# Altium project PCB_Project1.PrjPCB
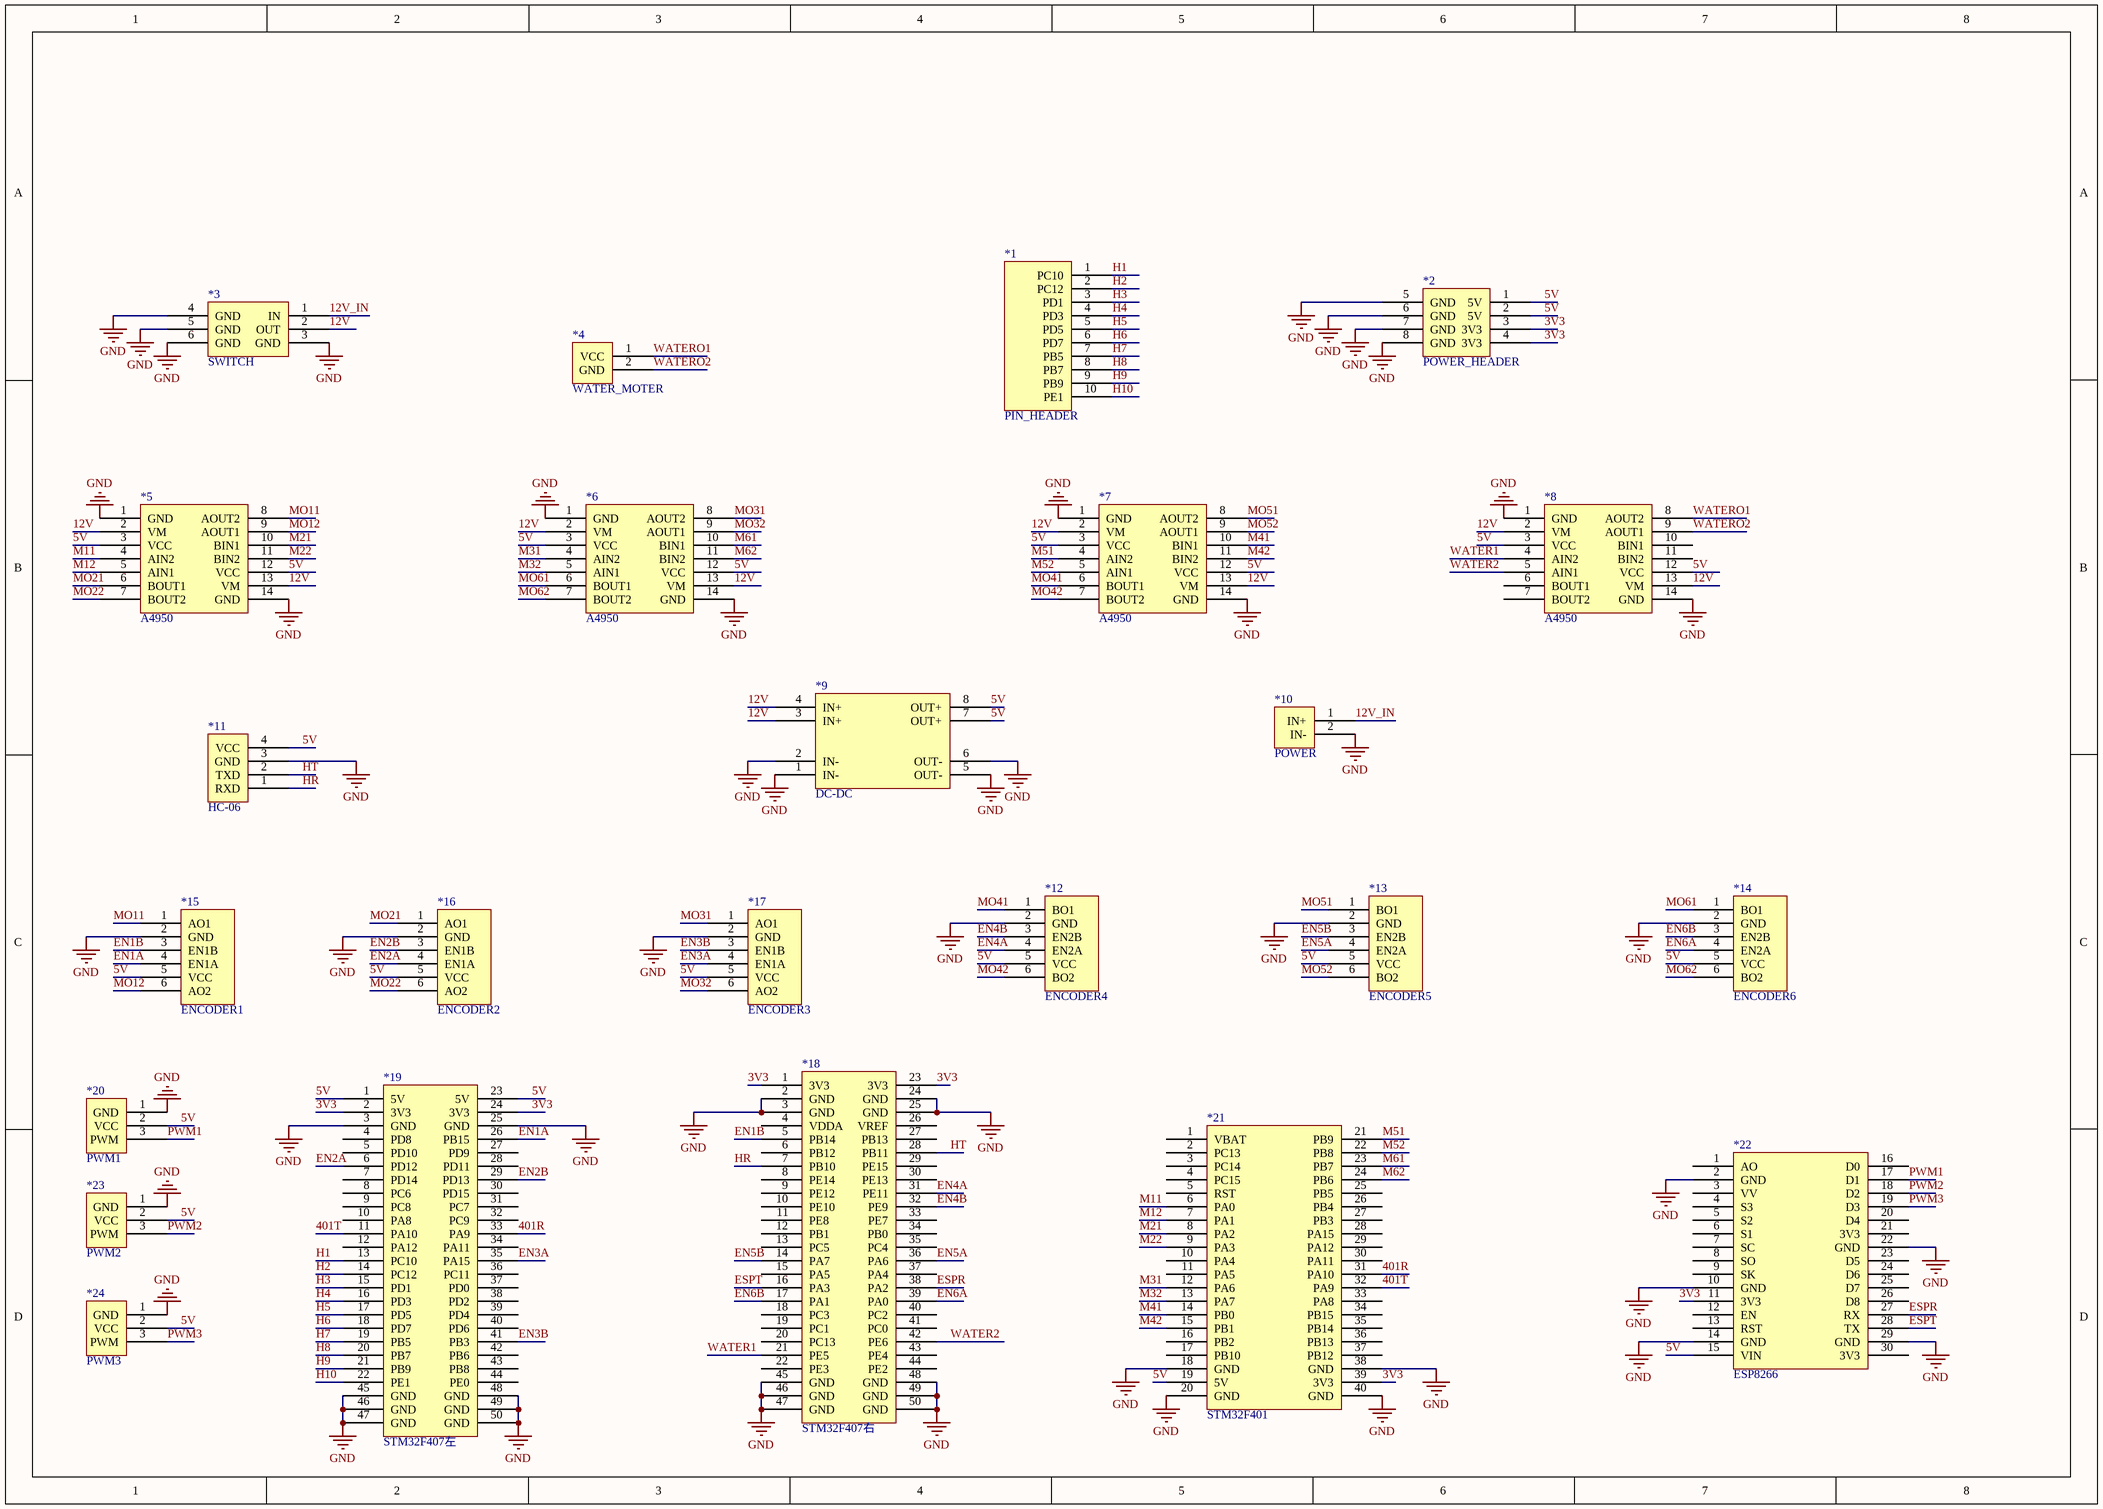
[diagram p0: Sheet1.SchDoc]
1 sheet, 24 parts. Net scope: global (net labels, ports and power ports of the same name join across sheets).
Board file: PCB1.PcbDoc

## Sheet Sheet1.SchDoc
size A3

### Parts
*1  PIN_HEADER  [PIN_HEADER]
*2  POWER_HEADER  [POWER_HEADER]
*3  SWITCH  [SIWITCH]
*4  WATER_MOTER  [WATER_HEADER]
*5  A4950  [A4950]
*6  A4950  [A4950]
*7  A4950  [A4950]
*8  A4950  [A4950]
*9  DC-DC  [DC-DC]
*10  POWER  [POWER]
*11  HC-06  [HC-06]
*12  ENCODER4  [ENCODER2]
*13  ENCODER5  [ENCODER2]
*14  ENCODER6  [ENCODER2]
*15  ENCODER1  [ENCODER1]
*16  ENCODER2  [ENCODER1]
*17  ENCODER3  [ENCODER1]
*18  STM32F407右  [STM32F407左]
*19  STM32F407左  [STM32F407左]
*20  PWM1  [PWM]
*21  STM32F401  [STM32F401CCU6]
*22  ESP8266  [ESP]
*23  PWM2  [PWM]
*24  PWM3  [PWM]

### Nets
GND: *2.5(GND) *2.6(GND) *2.7(GND) *2.8(GND) *3.3(GND) *3.4(GND) *3.5(GND) *3.6(GND) *5.1(GND) *5.14(GND) *6.1(GND) *6.14(GND) *7.1(GND) *7.14(GND) *8.1(GND) *8.14(GND) *9.1(IN-) *9.2(IN-) *9.5(OUT-) *9.6(OUT-) *10.2(IN-) *11.3(GND) *12.2(GND) *13.2(GND) *14.2(GND) *15.2(GND) *16.2(GND) *17.2(GND) *18.2(GND) *18.3(GND) *18.24(GND) *18.25(GND) *18.45(GND) *18.46(GND) *18.47(GND) *18.48(GND) *18.49(GND) *18.50(GND) *19.3(GND) *19.25(GND) *19.45(GND) *19.46(GND) *19.47(GND) *19.48(GND) *19.49(GND) *19.50(GND) *20.1(GND) *21.18(GND) *21.20(GND) *21.38(GND) *21.40(GND) *22.2(GND) *22.10(GND) *22.14(GND) *22.22(GND) *22.29(GND) *23.1(GND) *24.1(GND)
3V3: *2.3(3V3) *2.4(3V3) *18.1(3V3) *18.23(3V3) *19.2(3V3) *19.24(3V3) *21.39(3V3) *22.11(3V3)
5V: *2.1(5V) *2.2(5V) *5.3(VCC) *5.12(VCC) *6.3(VCC) *6.12(VCC) *7.3(VCC) *7.12(VCC) *8.3(VCC) *8.12(VCC) *9.7(OUT+) *9.8(OUT+) *11.4(VCC) *12.5(VCC) *13.5(VCC) *14.5(VCC) *15.5(VCC) *16.5(VCC) *17.5(VCC) *19.1(5V) *19.23(5V) *20.2(VCC) *21.19(5V) *22.15(VIN) *23.2(VCC) *24.2(VCC)
12V: *3.2(OUT) *5.2(VM) *5.13(VM) *6.2(VM) *6.13(VM) *7.2(VM) *7.13(VM) *8.2(VM) *8.13(VM) *9.3(IN+) *9.4(IN+)
12V_IN: *3.1(IN) *10.1(IN+)
401R: *19.33(PA9) *21.31(PA10)
401T: *19.11(PA10) *21.32(PA9)
EN1A: *15.4(EN1A) *19.26(PB15)
EN1B: *15.3(EN1B) *18.5(PB14)
EN2A: *16.4(EN1A) *19.6(PD12)
EN2B: *16.3(EN1B) *19.29(PD13)
EN3A: *17.4(EN1A) *19.35(PA15)
EN3B: *17.3(EN1B) *19.41(PB3)
EN4A: *12.4(EN2A) *18.31(PE11)
EN4B: *12.3(EN2B) *18.32(PE9)
EN5A: *13.4(EN2A) *18.36(PA6)
EN5B: *13.3(EN2B) *18.14(PA7)
EN6A: *14.4(EN2A) *18.39(PA0)
EN6B: *14.3(EN2B) *18.17(PA1)
ESPR: *18.38(PA2) *22.27(RX)
ESPT: *18.16(PA3) *22.28(TX)
H1: *1.1(PC10) *19.13(PC10)
H2: *1.2(PC12) *19.14(PC12)
H3: *1.3(PD1) *19.15(PD1)
H4: *1.4(PD3) *19.16(PD3)
H5: *1.5(PD5) *19.17(PD5)
H6: *1.6(PD7) *19.18(PD7)
H7: *1.7(PB5) *19.19(PB5)
H8: *1.8(PB7) *19.20(PB7)
H9: *1.9(PB9) *19.21(PB9)
H10: *1.10(PE1) *19.22(PE1)
HR: *11.1(RXD) *18.7(PB10)
HT: *11.2(TXD) *18.28(PB11)
M11: *5.4(AIN2) *21.6(PA0)
M12: *5.5(AIN1) *21.7(PA1)
M21: *5.10(BIN1) *21.8(PA2)
M22: *5.11(BIN2) *21.9(PA3)
M31: *6.4(AIN2) *21.12(PA6)
M32: *6.5(AIN1) *21.13(PA7)
M41: *7.10(BIN1) *21.14(PB0)
M42: *7.11(BIN2) *21.15(PB1)
M51: *7.4(AIN2) *21.21(PB9)
M52: *7.5(AIN1) *21.22(PB8)
M61: *6.10(BIN1) *21.23(PB7)
M62: *6.11(BIN2) *21.24(PB6)
MO11: *5.8(AOUT2) *15.1(AO1)
MO12: *5.9(AOUT1) *15.6(AO2)
MO21: *5.6(BOUT1) *16.1(AO1)
MO22: *5.7(BOUT2) *16.6(AO2)
MO31: *6.8(AOUT2) *17.1(AO1)
MO32: *6.9(AOUT1) *17.6(AO2)
MO41: *7.6(BOUT1) *12.1(BO1)
MO42: *7.7(BOUT2) *12.6(BO2)
MO51: *7.8(AOUT2) *13.1(BO1)
MO52: *7.9(AOUT1) *13.6(BO2)
MO61: *6.6(BOUT1) *14.1(BO1)
MO62: *6.7(BOUT2) *14.6(BO2)
PWM1: *20.3(PWM) *22.17(D1)
PWM2: *22.18(D2) *23.3(PWM)
PWM3: *22.19(D3) *24.3(PWM)
WATER1: *8.4(AIN2) *18.21(PE5)
WATER2: *8.5(AIN1) *18.42(PE6)
WATERO1: *4.1(VCC) *8.8(AOUT2)
WATERO2: *4.2(GND) *8.9(AOUT1)

Not connected (* = marked no-connect by the designer): *8 6(BOUT1) 7(BOUT2) 10(BIN1) 11(BIN2); *18 4(VDDA) 6(PB12) 8(PE14) 9(PE12) 10(PE10) 11(PE8) 12(PB1) 13(PC5) 15(PA5) 18(PC3) 19(PC1) 20(PC13) 22(PE3) 26(VREF) 27(PB13) 29(PE15) 30(PE13) 33(PE7) 34(PB0) 35(PC4) 37(PA4) 40(PC2) 41(PC0) 43(PE4) 44(PE2); *19 4(PD8) 5(PD10) 7(PD14) 8(PC6) 9(PC8) 10(PA8) 12(PA12) 27(PD9) 28(PD11) 30(PD15) 31(PC7) 32(PC9) 34(PA11) 36(PC11) 37(PD0) 38(PD2) 39(PD4) 40(PD6) 42(PB6) 43(PB8) 44(PE0); *21 1(VBAT) 2(PC13) 3(PC14) 4(PC15) 5(RST) 10(PA4) 11(PA5) 16(PB2) 17(PB10) 25(PB5) 26(PB4) 27(PB3) 28(PA15) 29(PA12) 30(PA11) 33(PA8) 34(PB15) 35(PB14) 36(PB13) 37(PB12); *22 1(AO) 3(VV) 4(S3) 5(S2) 6(S1) 7(SC) 8(SO) 9(SK) 12(EN) 13(RST) 16(D0) 20(D4) 21(3V3) 23(D5) 24(D6) 25(D7) 26(D8) 30(3V3)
